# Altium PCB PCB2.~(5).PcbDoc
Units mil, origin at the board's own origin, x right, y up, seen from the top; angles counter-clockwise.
Board outline 6000 x 4000 mil, 2 copper layers (Top Layer, Bottom Layer); 0 components, 0 nets, 0 pads, 0 vias.
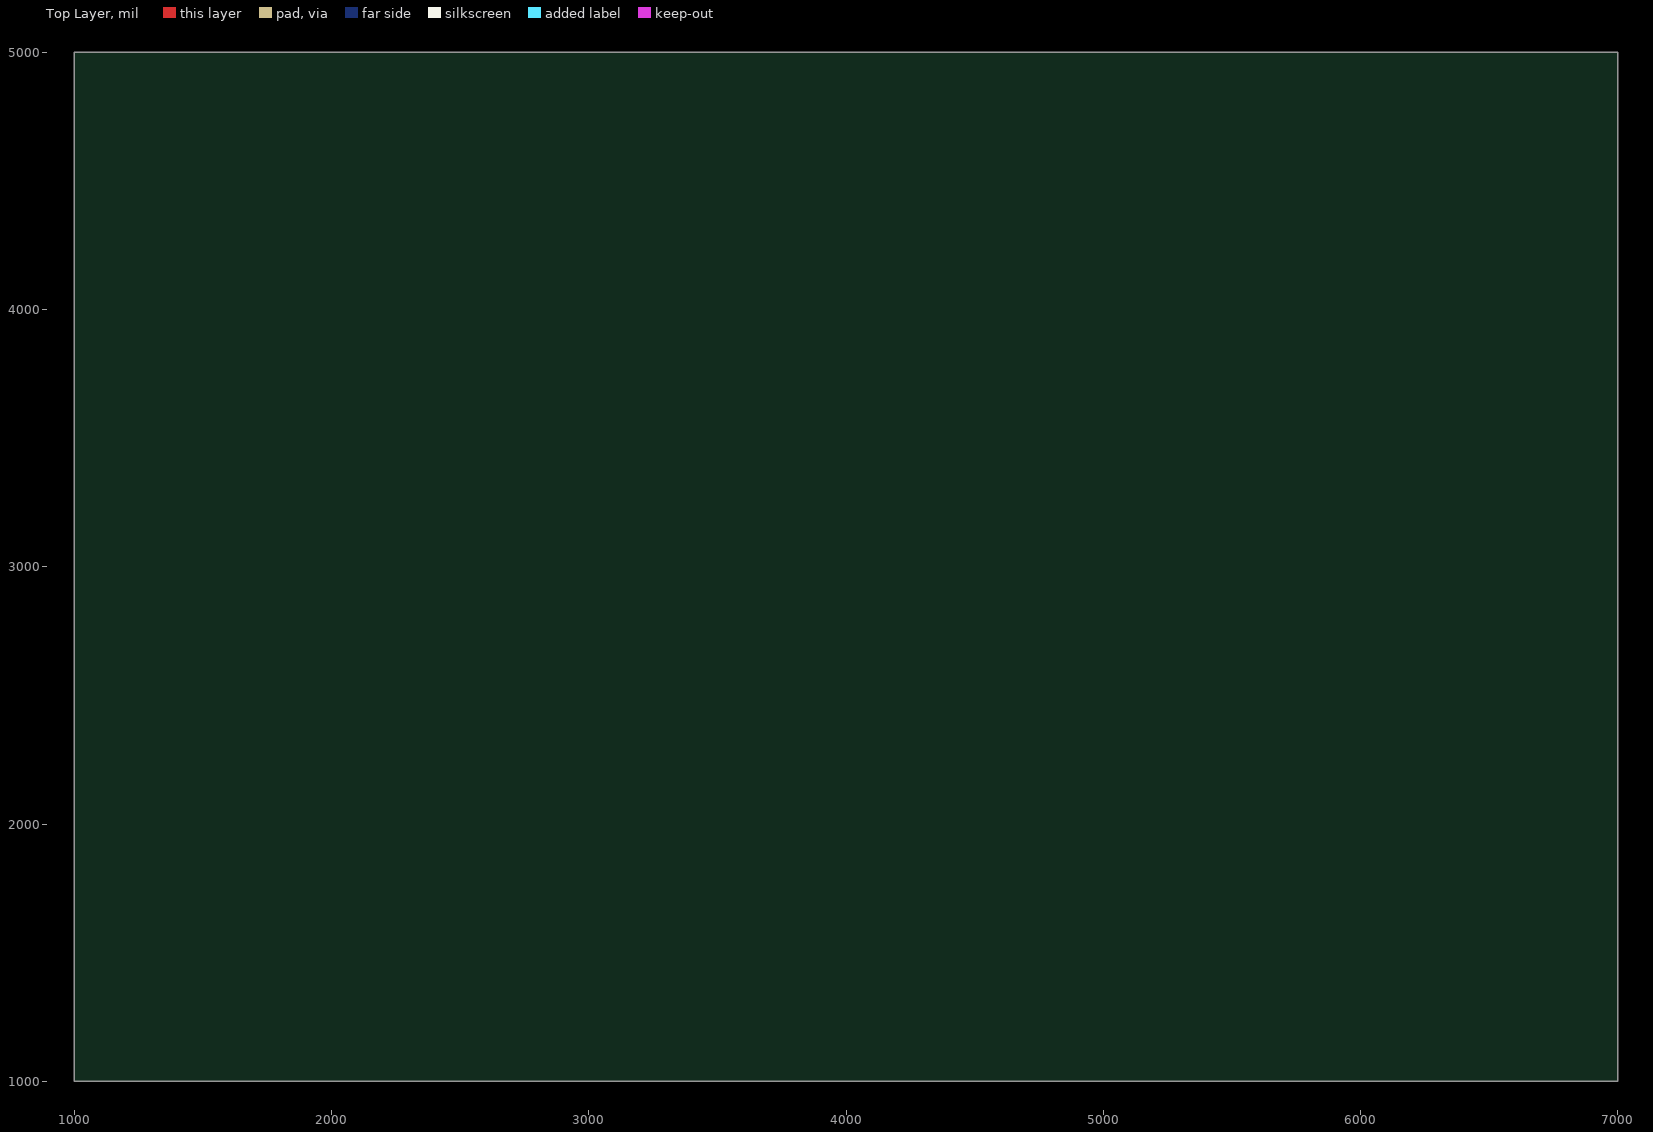
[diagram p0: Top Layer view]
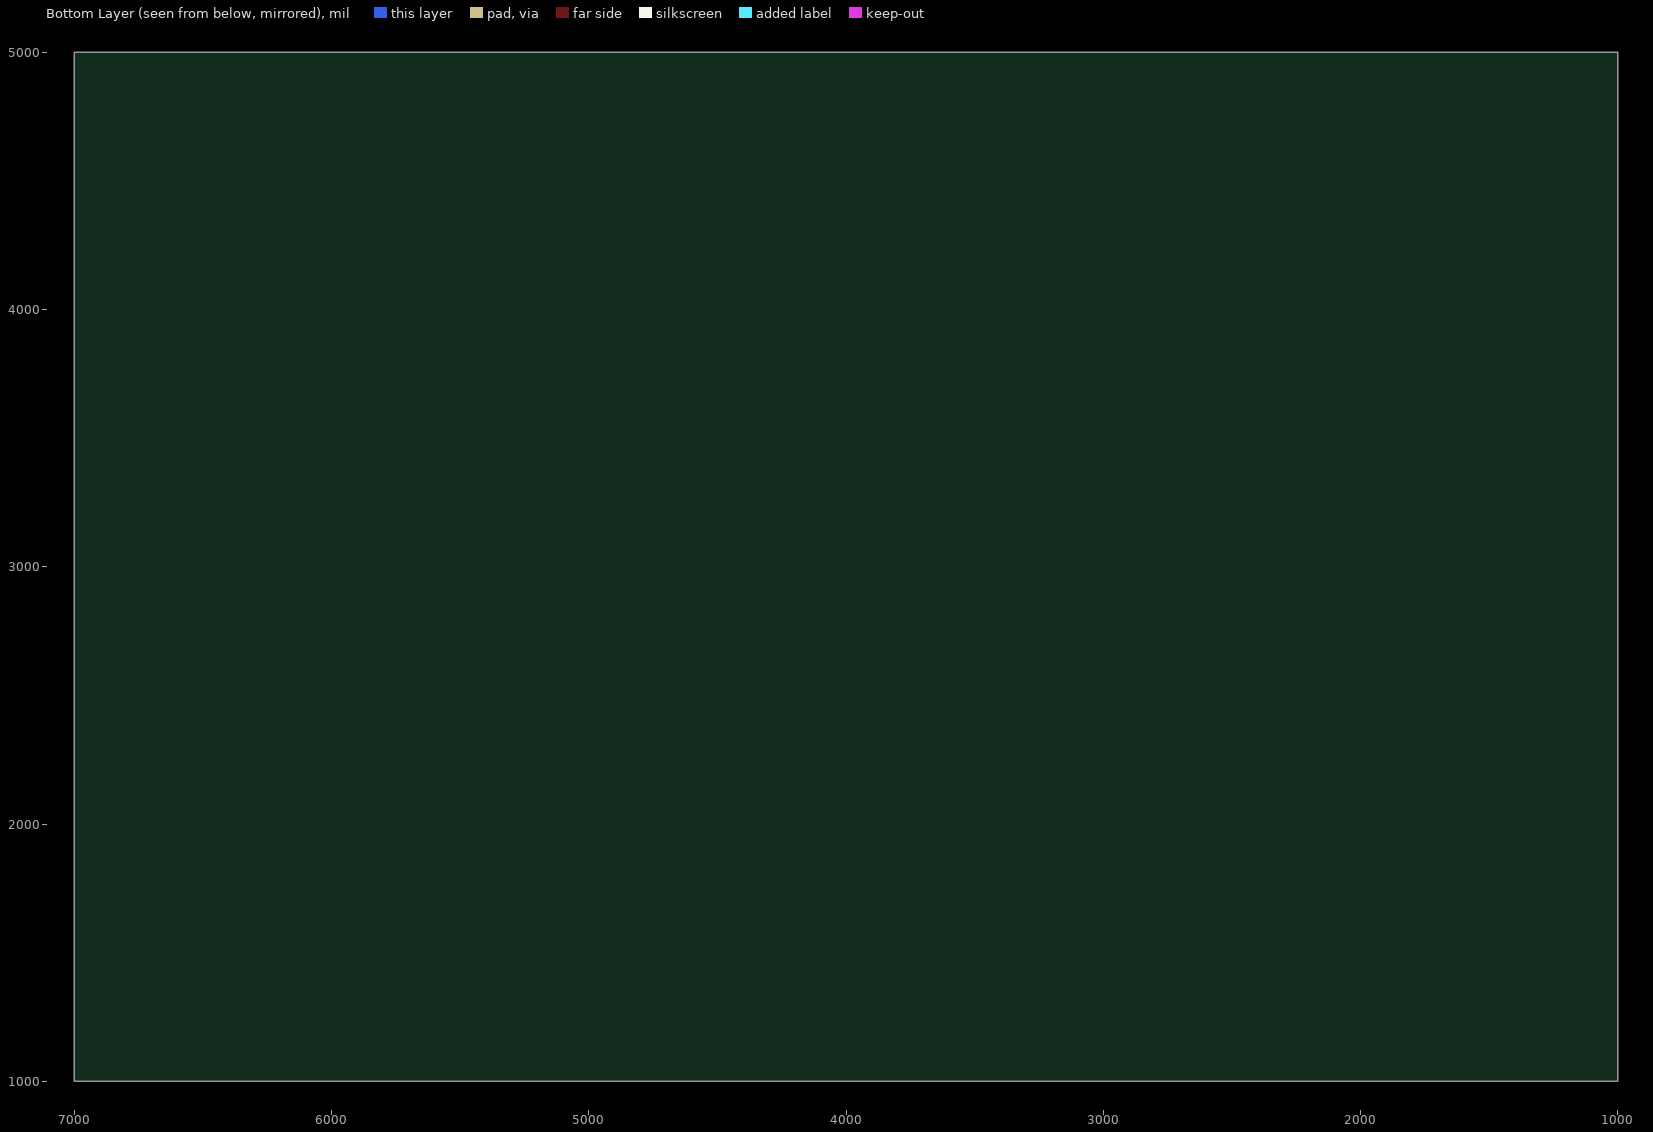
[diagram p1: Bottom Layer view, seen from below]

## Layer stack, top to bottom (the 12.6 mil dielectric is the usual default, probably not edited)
Top Solder: solder mask 0.4, Solder Resist, Dk 3.5
Top Layer: signal copper 1.4
Dielectric 1: dielectric 12.6, FR-4, Dk 4.8
Bottom Layer: signal copper 1.4
Bottom Solder: solder mask 0.4, Solder Resist, Dk 3.5

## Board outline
1000,1000 7000,1000 7000,5000 1000,5000

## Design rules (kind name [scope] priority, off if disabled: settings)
Clearance [All] p1: gap=10
PolygonConnect [All] p1: connectstyle=Relief reliefconductorwidth=10 reliefentries=4 polygonreliefangle="90 Angle" airgapwidth=10
RoutingVias [All] p1: holewidth=28 width=50 viastyle="Through Hole" minholewidth=28 minwidth=50 maxholewidth=28 maxwidth=50
SolderMaskExpansion [All] p1: expansion=4
Width [All] p1: maxlimit=10 minlimit=10 preferedwidth=10
30 further rules are at their usual default settings.

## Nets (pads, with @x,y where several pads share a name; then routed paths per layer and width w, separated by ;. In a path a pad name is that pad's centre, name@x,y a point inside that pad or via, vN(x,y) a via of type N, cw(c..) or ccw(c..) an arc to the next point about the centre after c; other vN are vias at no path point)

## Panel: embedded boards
"..\Students\4\ELECH402_Labo6 AS-Ni\Labo6 AS-Ni\PCB_Project\PCB1.PcbDoc" at 3850,3850, 1 rows x 1 columns, spacing 3149.61 x 3149.61, rotation 0
"..\Students\3\Project_JLM_H402\PCB1.PcbDoc" at 1000,3850, 1 rows x 1 columns, spacing 3149.61 x 3149.61, rotation 0
"..\Students\1\PCB_Project\PCB1.PcbDoc" at 3850,1000, 1 rows x 1 columns, spacing 3149.61 x 3149.61, rotation 0
"..\Students\2\PCB_Project\PCB1.PcbDoc" at 1000,1000, 1 rows x 1 columns, spacing 3149.61 x 3149.61, rotation 0
"" at 1735,1835, 2 rows x 2 columns, spacing 3149.61 x 3149.61, rotation 0
"" at 1730,1295, 2 rows x 2 columns, spacing 3149.61 x 3149.61, rotation 0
